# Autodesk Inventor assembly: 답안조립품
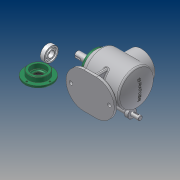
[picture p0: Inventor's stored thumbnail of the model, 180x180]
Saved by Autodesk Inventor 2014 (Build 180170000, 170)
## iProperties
Created: 2016-04
Part Number: 답안조립품
Document SubType Name: Assembly
Designer: owner
Author: owner
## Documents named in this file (13)
- C:\Users\owner\Desktop\460407V1016\답안조립품.iam
- C:\Users\owner\Desktop\460407V1016\메인 축.ipt
- 메인 축.ipt
- C:\Users\owner\Desktop\460407V1016\키 5x5.ipt
- C:\Users\owner\Desktop\460407V1016\커버.ipt
- C:\Users\owner\Desktop\460407V1016\오일실 17 32 8.ipt
- C:\Users\owner\Desktop\460407V1016\베어링 6203.ipt
- C:\Users\owner\Desktop\460407V1016\메인 베벨기어.ipt
- C:\Users\owner\Desktop\460407V1016\본체.ipt
- C:\Users\owner\Desktop\460407V1016\M4.ipt
- C:\Users\owner\Desktop\460407V1016\서브 축.ipt
- 서브 축.ipt
- C:\Users\owner\Desktop\460407V1016\키 4x4.ipt
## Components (4 placed, 1 different names)
1. M4:1
2. M4:2
3. M4:3
4. M4:4
## Named parameters: d3_d2 = 0
